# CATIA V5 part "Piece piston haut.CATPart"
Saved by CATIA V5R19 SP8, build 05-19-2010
Part number: Piece piston haut
Bounding box of the stored display mesh (mm): x -46.239 to 21.335, y -52.762 to 80.963, z -12 to 12
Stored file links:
  G:\EU_thinkMotion\CFAO_2010\MMS_groupe3\MMS_groupe3\A reprendre\lpastor\lpastor\Piece piston haut.CATPart
  C:\Users\Loïc\Documents\IFMA\Cours 2A\CFAO\Thinkmotion\Fourche avant.CATProduct
  G:\EU_thinkMotion\CFAO_2010\MMS_groupe3\MMS_groupe3\A reprendre\lpastor\lpastor\Pieces.CATProduct
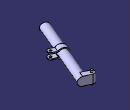
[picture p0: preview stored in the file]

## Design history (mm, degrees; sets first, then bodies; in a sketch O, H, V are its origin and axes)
External parameters (linked from other documents)
  External.Parametre_rayon_exterieur_amortisseur_haut = 0.008
  External.Parametre_rayon_interieur_amortisseur_haut = 0.005
Set1
  Line1 "Droite GH (piston haut)": linked copy from another document
  Plane1: linked copy from another document
  Plane2: linked copy from another document
  Line2 "Droite C (piston haut)": linked copy from another document
  Plane3: linked copy from another document
  Line3 "Droite B (piston haut)": linked copy from another document
  Plane4: linked copy from another document
  Line4 "Droite CH (piston haut)": linked copy from another document
Body1 (main body)
  Sketch1 on Plane1, origin (29.5971, 62.5162, 0), H (-0.9202, 0.3914, 0), V (0, 0, 1)
    circle A1 centre (19.1223, 0) radius 8
    point P1 (19.1223, 0)
    reference projected point E1 (19.1223, 0) from Line1
    radius A1 = 8 {= External.Parametre_rayon_exterieur_amortisseur_haut}
    coincidence: P1 E1
  Pad1: profile Sketch1, direction (0.3914, 0.9202, 0), up to Plane4
  Sketch2 on Plane2, origin (0, 0, 8), H (1, 0, 0), V (0, 1, 0)
    line L1 (21.3353, 71.5092) -> (-0.0432, 80.6012)
    arc A1 centre (-2, 76) radius 5 from (-0.0432, 80.6012) to (-3.9568, 71.3988) ccw
    point P3 (-2, 76)
    line L2 (-3.9568, 71.3988) -> (17.4216, 62.3068)
    line L3 (17.4216, 62.3068) -> (21.3353, 71.5092)
    reference intersected line E1 through (22.0701, 65.7173) direction (-0.9202, 0.3914) from Plane1
    reference projected line E2 (-78.8404, -143.5978) -> (12, 70) from Line1
    reference projected point E3 (-2, 76) from Line2
    reference projected point E4 (-2, 76) from Line2
    distance L1 L2 = 10
    distance E2 L3 = 8
    tangency: A1 L1, L2 A1
    parallelism: L2 E1
    perpendicularity: L3 L2, L1 L3
    coincidence: P3 E3
    concentricity: A1 E4
  Sketch3 on Plane1, origin (22.0701, 65.7173, 0), H (-0.9202, 0.3914, 0), V (0, 0, 1)
    line L1 (76.1745, 8) -> (10.943, 8)
    arc A1 centre (10.943, 0) radius 8 from (10.943, 8) to (2.943, 0) ccw
    line L2 (2.943, 0) -> (76.1745, 0)
    line L3 (76.1745, 0) -> (76.1745, 8)
    reference projected line E1 (26.1745, 0) -> (10.943, 0) from Line4
    reference intersected line E2 through (0, 8) direction (-1, 0) from Plane2
    reference projected point E3 (10.943, 0) from Line1
    reference projected line E4 (26.1745, -50) -> (26.1745, 50) from Line2
    distance L3 E4 = 50
    horizontal: L1 H, L2 H
    tangency: A1 L1
    vertical: L3 V
    coincidence: L2 E1, L1 E2
    concentricity: A1 E3
  SolidCombine1: FirstComponentProfile Sketch2, FirstComponentDirection Sketch2, SecondComponentProfile Sketch3, SecondComponentDirection Sketch3
  Sketch4 on Plane2, origin (0, 0, 8), H (1, 0, 0), V (0, 1, 0)
    circle A1 centre (-2, 76) radius 2
    point P1 (-2, 76)
    reference projected point E1 (-2, 76) from Line2
    radius A1 = 2
    coincidence: P1 E1
  Pad2: profile Sketch4, direction (0, 0, 1), length 4
  Sketch5 on Plane4, origin (-21.2803, -57.1144, 0), H (-0.9202, 0.3914, 0), V (0, 0, 1)
    circle A1 centre (19.1223, 0) radius 5
    point P1 (19.1223, 0)
    reference projected point E1 (19.1223, 0) from Line1
    radius A1 = 5 {= External.Parametre_rayon_interieur_amortisseur_haut}
    coincidence: P1 E1
  Pocket1: profile Sketch5, direction (0.3914, 0.9202, 0), length 120
  Sketch6 on Plane3, origin (0, 0, 4), H (1, 0, 0), V (0, 1, 0)
    line L1 (-21.9693, 14.7767) -> (-25.883, 5.5743)
    line L2 (-25.883, 5.5743) -> (-1.9568, -4.6012)
    arc A1 centre (0, 0) radius 5 from (-1.9568, -4.6012) to (1.9568, 4.6012) ccw
    point P4 (0, 0)
    line L3 (1.9568, 4.6012) -> (-21.9693, 14.7767)
    reference projected line E1 (-62, -104) -> (12, 70) from Line1
    reference projected point E2 (0, 0) from Line3
    length L1 = 10
    length L3 = 26
    perpendicularity: L2 L1, L1 L3
    tangency: A1 L2, L3 A1
    parallelism: L1 E1
    coincidence: P4 E2
  Sketch7 on Plane1, origin (27.0483, 63.6001, 0), H (-0.9202, 0.3914, 0), V (0, 0, 1)
    arc A1 centre (16.3527, 0) radius 10 from (26.3527, 0) to (8.3527, 6) ccw
    point P1 (16.3527, 0)
    arc A2 centre (16.3527, 0) radius 8 from (24.3527, 0) to (9.4245, 4) ccw
    point P2 (16.3527, 0)
    line L1 (8.3527, 6) -> (-4.6473, 6)
    line L2 (-4.6473, 6) -> (-4.6473, 4)
    line L3 (-4.6473, 4) -> (9.4245, 4)
    reference projected point E1 (16.3527, 0) from Line1
    reference intersected line E2 through (0, 4) direction (-1, 0) from Plane3
    line L4 (24.3527, 0) -> (26.3527, 0)
    reference projected point E3 (16.3527, 0) from Line1
    radius A2 = 8 {= External.Parametre_rayon_exterieur_amortisseur_haut}
    radius A1 = 10 {= External.Parametre_rayon_exterieur_amortisseur_haut +0.002}
    distance L1 L3 = 2
    coincidence: P2 P1, P2 E1, L3 E2, L4 E3
    horizontal: L4 H
  SolidCombine2: FirstComponentProfile Sketch6, FirstComponentDirection Sketch6, SecondComponentProfile Sketch7, SecondComponentDirection Sketch7
  Sketch8 on face of SolidCombine2 from Sketch7.L1, origin (0, 0, 6), H (1, 0, 0), V (0, 1, 0)
    circle A1 centre (0, 0) radius 2
    reference projected arc E1 centre (0, 0) radius 5 from (4.9985, -0.1213) to (1.9568, 4.6012) ccw from edge [face of SolidCombine2 from Sketch6.A1 | face of SolidCombine2 from Sketch7.L1]
    radius A1 = 2
    concentricity: A1 E1
  Pocket2: profile Sketch8, direction (0, 0, -1), through (limit type 3)
  Mirror1: of SolidCombine1, Pad2, about face of SolidCombine1 from Sketch3.L2
  Mirror2: of SolidCombine2, Pocket2, about face of SolidCombine2 from Sketch7.L4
